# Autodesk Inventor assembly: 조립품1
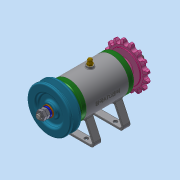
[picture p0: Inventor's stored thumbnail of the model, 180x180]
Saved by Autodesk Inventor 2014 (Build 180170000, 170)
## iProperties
Created: 2021-12
Part Number: 조립품1
Document SubType Name: Assembly
Designer: dg
Author: dg
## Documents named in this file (16)
- C:\Users\dg\Desktop\711206V1025\조립품1.iam
- C:\Users\dg\Desktop\711206V1025\부품1.ipt
- C:\Users\dg\Desktop\711206V1025\니플 M6 x 0.75.ipt
- C:\Users\dg\Desktop\711206V1025\축.ipt
- C:\Users\dg\Desktop\711206V1025\키 3 x 3.ipt
- C:\Users\dg\Desktop\711206V1025\V벨트풀리.ipt
- C:\Users\dg\Desktop\711206V1025\와셔 8 x 17.ipt
- C:\Users\dg\Desktop\711206V1025\스프링와셔 8.ipt
- C:\Users\dg\Desktop\711206V1025\너트 M8.ipt
- C:\Users\dg\Desktop\711206V1025\스프로킷.ipt
- C:\Users\dg\Desktop\711206V1025\베어링 6002.ipt
- C:\Users\dg\Desktop\711206V1025\커버.ipt
- C:\Users\dg\Desktop\711206V1025\볼트 M4 x 12.ipt
- C:\Users\dg\Desktop\711206V1025\오일 실 15 x 25 x 7.ipt
- C:\Users\dg\Desktop\711206V1025\와셔 6 x 11.5.ipt
- C:\Users\dg\Desktop\711206V1025\볼트 M6 x 8.ipt
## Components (11 placed, 3 different names)
1. V벨트풀리:1
2. KS B 2023 6002 - 15 x 32 x 9:1
3. KS B 2023 6002 - 15 x 32 x 9:2
4. ISO 4762 M4 x 12:1
5. ISO 4762 M4 x 12:2
6. ISO 4762 M4 x 12:3
7. ISO 4762 M4 x 12:4
8. ISO 4762 M4 x 12:5
9. ISO 4762 M4 x 12:6
10. ISO 4762 M4 x 12:7
11. ISO 4762 M4 x 12:8
